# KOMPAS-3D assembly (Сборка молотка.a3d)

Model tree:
1. Смещенная плоскость:1
     Расстояние = 12.5
2. Скругление:1
     Радиус = 1
3. Скругление:2
     Радиус = 1
4. Скругление:3
     Радиус = 1; Ориентация = 2

Referenced files in D:\твой стартап\Тексты на сайт\Чертежи\сборка молотка\: молоток.m3d, ручка молотка.m3d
